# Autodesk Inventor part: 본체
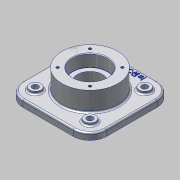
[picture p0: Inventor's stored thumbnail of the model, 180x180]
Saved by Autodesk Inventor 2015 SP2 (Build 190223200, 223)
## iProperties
Created: 2015-07
Part Number: 본체
Material: 알루미늄 6061
Document SubType Name: Modeling
Designer: AMC
Density: 2.7 g/cm^3
Appearance: 알루미늄 - 평지
Mass: 1459.27 g
Surface Area: 800.934 cm^2
Volume: 540.471 cm^3
Author: AMC
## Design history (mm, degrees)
sketch "스케치1"
  geometry: L1 (-75, -75)-(75, -75); L2 (75, -75)-(75, 75); L3 (75, 75)-(-75, 75); L4 (-75, 75)-(-75, -75); L5 (-75, -75)-(75, 75); L6 (75, -75)-(-75, 75); 1 further point
  constraints: 12 end point, 2 midpoint, 2 parallel, 1 horizontal, 1 perpendicular
  dimensions: "d0" = 150 distance of L3.end L2.end; "d1" = 150 distance of L2.end L1.end
extrude "돌출1" new body sketch "스케치1" distance "d2" = 12; taper "d3" = 0 deg
sketch "스케치2"
  geometry: C1 r 50 at (0, 0); 1 further point
  constraints: 1 centre point, 1 coincident
  dimensions: "d4" = 100 diameter of C1
extrude "돌출2" join sketch "스케치2" distance "d5" = 47; taper "d7" = 0 deg; dims "d6" = 23, "d8" = 0
hole "구멍1" diameter "d11" = 45; stored, may be unused: countersink angle "d15" = 90 deg, drill point angle "d17" = 118 deg; dims "d9" = 10, "d10" = 10, "d12" = 6, "d13" = 62, "d14" = 22, "d16" = 9.525
hole "구멍2" diameter "d20" = 45; stored, may be unused: countersink angle "d24" = 90 deg, drill point angle "d26" = 118 deg; dims "d18" = 10, "d19" = 10, "d21" = 6, "d22" = 62, "d23" = 22, "d25" = 9.525
sketch "스케치3"
  geometry: L1 (-49, -49)-(49, -49); L2 (49, -49)-(49, 49); L3 (49, 49)-(-49, 49); L4 (-49, 49)-(-49, -49); L5 (-49, -49)-(49, 49); L6 (49, -49)-(-49, 49); C1 r 10 at (49, 49); C2 r 10 at (49, -49); C3 r 10 at (-49, -49); C4 r 10 at (-49, 49); 1 further point
  constraints: 12 end point, 4 centre point, 4 coincident, 2 midpoint, 2 parallel, 1 horizontal, 1 perpendicular
  dimensions: "d31" = 98 distance of L3.end L2.end; "d32" = 98 distance of L2.end L1.end; "d33" = 20 diameter of C1; "d34" = 20 diameter of C2; "d35" = 20 diameter of C3; "d36" = 20 diameter of C4
extrude "돌출3" join sketch "스케치3" distance "d37" = 5; taper "d38" = 0 deg
hole "구멍3" diameter "d41" = 11; stored, may be unused: countersink angle "d45" = 90 deg, drill point angle "d47" = 118 deg; dims "d39" = 10, "d40" = 10, "d42" = 6, "d43" = 62, "d44" = 22, "d46" = 9.525
hole "구멍4" diameter "d50" = 11; stored, may be unused: countersink angle "d54" = 90 deg, drill point angle "d56" = 118 deg; dims "d48" = 10, "d49" = 10, "d51" = 6, "d52" = 62, "d53" = 22, "d55" = 9.525
hole "구멍5" diameter "d59" = 11; stored, may be unused: countersink angle "d63" = 90 deg, drill point angle "d65" = 118 deg; dims "d57" = 10, "d58" = 10, "d60" = 6, "d61" = 62, "d62" = 22, "d64" = 9.525
hole "구멍6" diameter "d68" = 11; stored, may be unused: countersink angle "d72" = 90 deg, drill point angle "d74" = 118 deg; dims "d66" = 10, "d67" = 10, "d69" = 6, "d70" = 62, "d71" = 22, "d73" = 9.525
sketch "스케치4"
  geometry: L1 (0, 0)-(41, 0); L2 (0, 0)-(28.991, 28.991); L3 (0, 0)-(41, 0); A1 r 41 centre (0, 0) between (41, 0) and (28.991, 28.991); 2 further points
  constraints: 6 end point, 2 coincident, 2 horizontal, 2 point on circle, 1 centre point, 1 equal length
  dimensions: "d75" = 82 diameter of A1; "d76" = 45 deg angle of L3 L2
hole "구멍7" sketch "스케치4" at (28.991, 28.991) diameter "d77" = 4.917; stored, may be unused: countersink angle "d81" = 90 deg, drill point angle "d83" = 118 deg; dims "d78" = 10, "d79" = 62, "d80" = 22, "d82" = 13
sketch "스케치5"
  geometry: L1 (0, 0)-(41, 0); L2 (0, 0)-(28.991, 28.991); L3 (0, 0)-(41, 0); A1 r 41 centre (0, 0) between (41, 0) and (28.991, 28.991); 2 further points
  constraints: 6 end point, 2 coincident, 2 horizontal, 2 point on circle, 1 centre point, 1 equal length
  dimensions: "d87" = 82 diameter of A1; "d88" = 45 deg angle of L3 L2
hole "구멍8" sketch "스케치5" at (28.991, 28.991) diameter "d89" = 4.917; stored, may be unused: countersink angle "d93" = 90 deg, drill point angle "d95" = 118 deg; dims "d90" = 10, "d91" = 62, "d92" = 22, "d94" = 13
sketch "스케치6"
  geometry: 2 further points
  constraints: 1 vertical alignment, 1 other
  dimensions: "d99" = 65 distance of point (0, 0) point (0, 65)
feature "엠보싱1" sketch "스케치6" dims "d0" = 150, "d1" = 150, "d100" = 1, "d101" = 0
fillet "모깎기1" dims "d102" = 30
fillet "모깎기2" dims "d103" = 0.3
chamfer "모따기1" distance "d104" = 1; stored, may be unused: second distance "d105" = 2, angle "d106" = 45 deg
fillet "모깎기3" dims "d107" = 3
fillet "모깎기4" dims "d108" = 3
fillet "모깎기5" dims "d109" = 3
node "솔리드1"
pattern_circular "원형 패턴1" dims angle "d85" = 360 deg
pattern_circular "원형 패턴2" dims angle "d97" = 360 deg
